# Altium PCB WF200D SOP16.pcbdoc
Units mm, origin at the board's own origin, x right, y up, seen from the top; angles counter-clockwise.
Board outline 19.85 x 23.96 mm, 2 copper layers (Top Layer, Bottom Layer); 1 components, 0 nets, 6 pads, 0 vias.
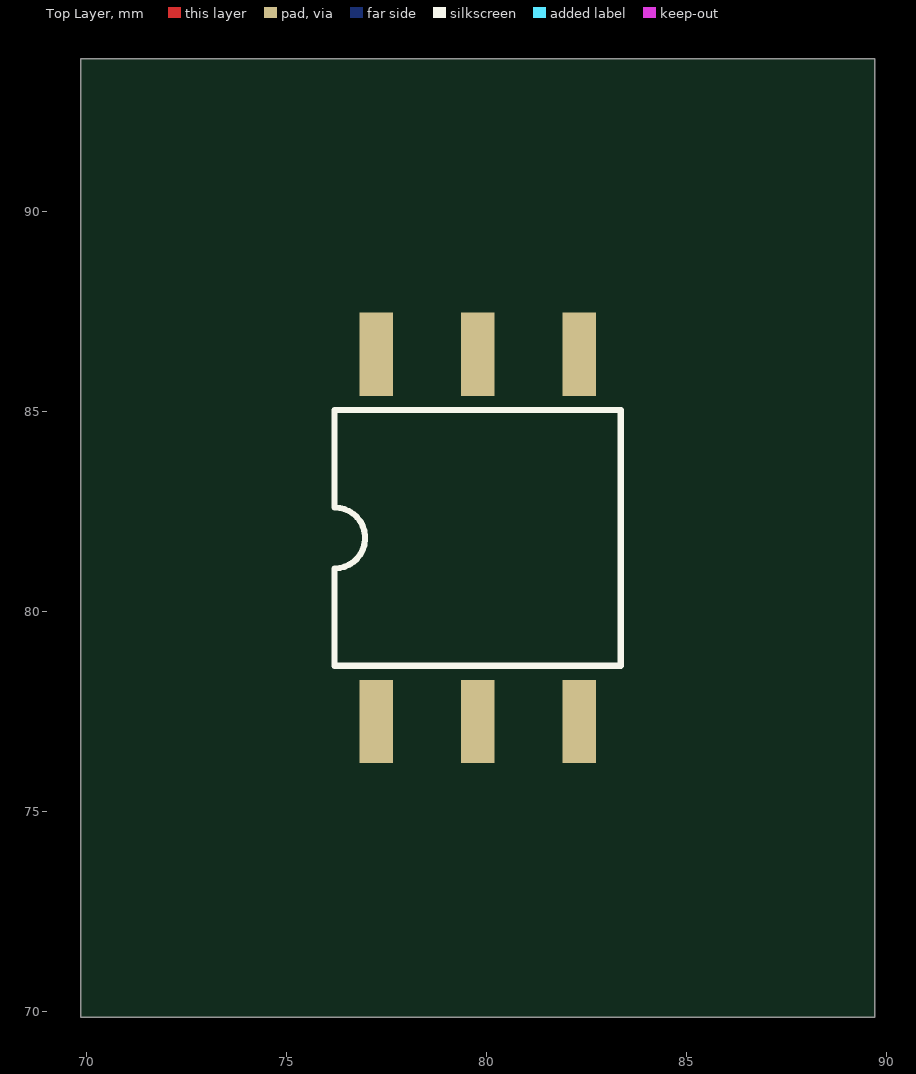
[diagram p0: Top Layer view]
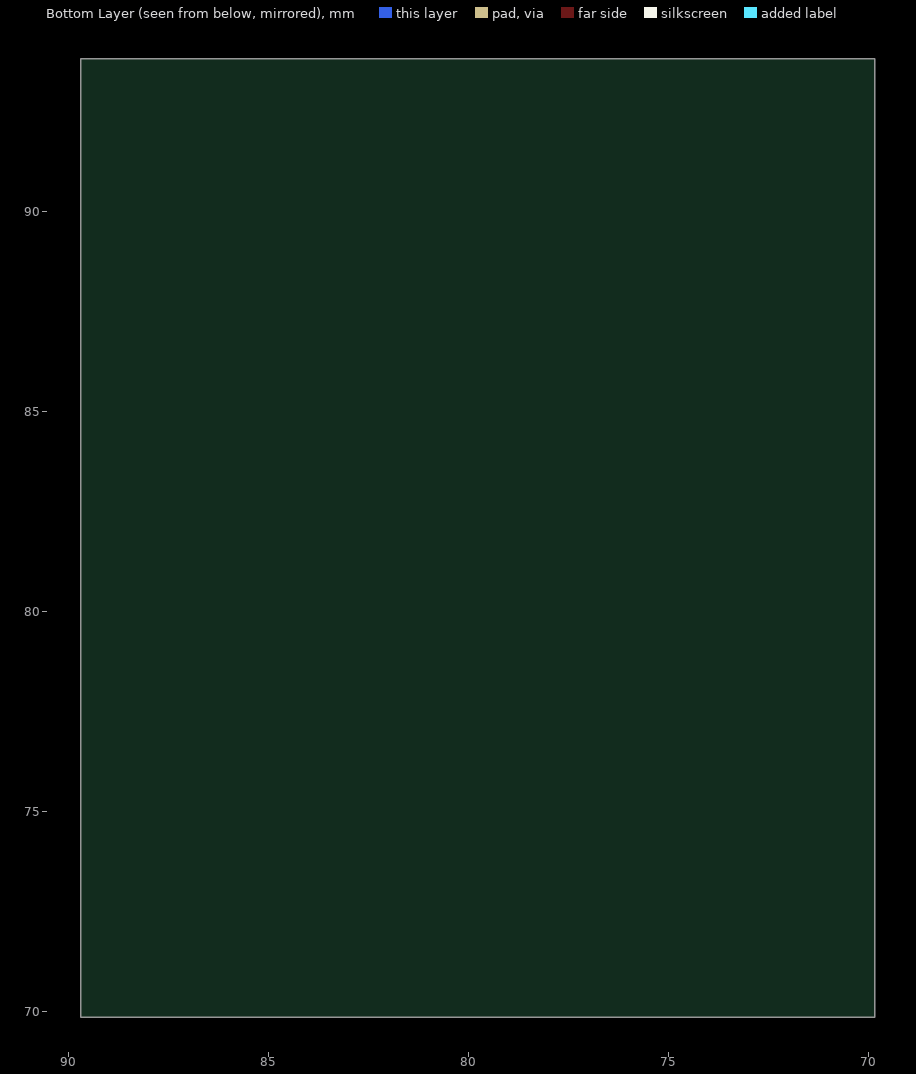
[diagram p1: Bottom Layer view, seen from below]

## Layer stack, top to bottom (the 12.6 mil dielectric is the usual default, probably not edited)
Top Layer: signal copper (thickness not stored)
Dielectric: dielectric 0.32, FR-4, Dk 4.8
Bottom Layer: signal copper (thickness not stored)

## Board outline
89.702,69.85 69.85,69.85 69.85,93.81 89.702,93.81

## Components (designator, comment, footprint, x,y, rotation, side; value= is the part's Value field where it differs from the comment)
? "SOP-6_L7.0-W7.0-P2.54-LS10.3-TL-CW" SOP-6_L7.0-W7.0-P2.54-LS10.3-TL-CW 79.776,81.83 r0 top

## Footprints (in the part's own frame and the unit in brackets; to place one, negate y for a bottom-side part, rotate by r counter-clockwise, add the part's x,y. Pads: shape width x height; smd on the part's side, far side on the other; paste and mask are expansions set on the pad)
SOP-6_L7.0-W7.0-P2.54-LS10.3-TL-CW [mm]
  rect 0.84x2.08 smd: 1(-2.54,4.59) 2(0,4.59) 3(2.54,4.59) 4(2.54,-4.59) 5(0,-4.59) 6(-2.54,-4.59)
  silkscreen extent -3.58,-3.2 3.58,3.2

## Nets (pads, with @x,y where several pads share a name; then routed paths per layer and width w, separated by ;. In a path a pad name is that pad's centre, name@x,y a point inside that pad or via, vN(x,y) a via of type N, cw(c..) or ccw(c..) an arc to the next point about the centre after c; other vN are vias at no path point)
pads on no net: ?.1 ?.2 ?.3 ?.4 ?.5 ?.6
